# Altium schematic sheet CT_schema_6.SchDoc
size 221 x 258 mm
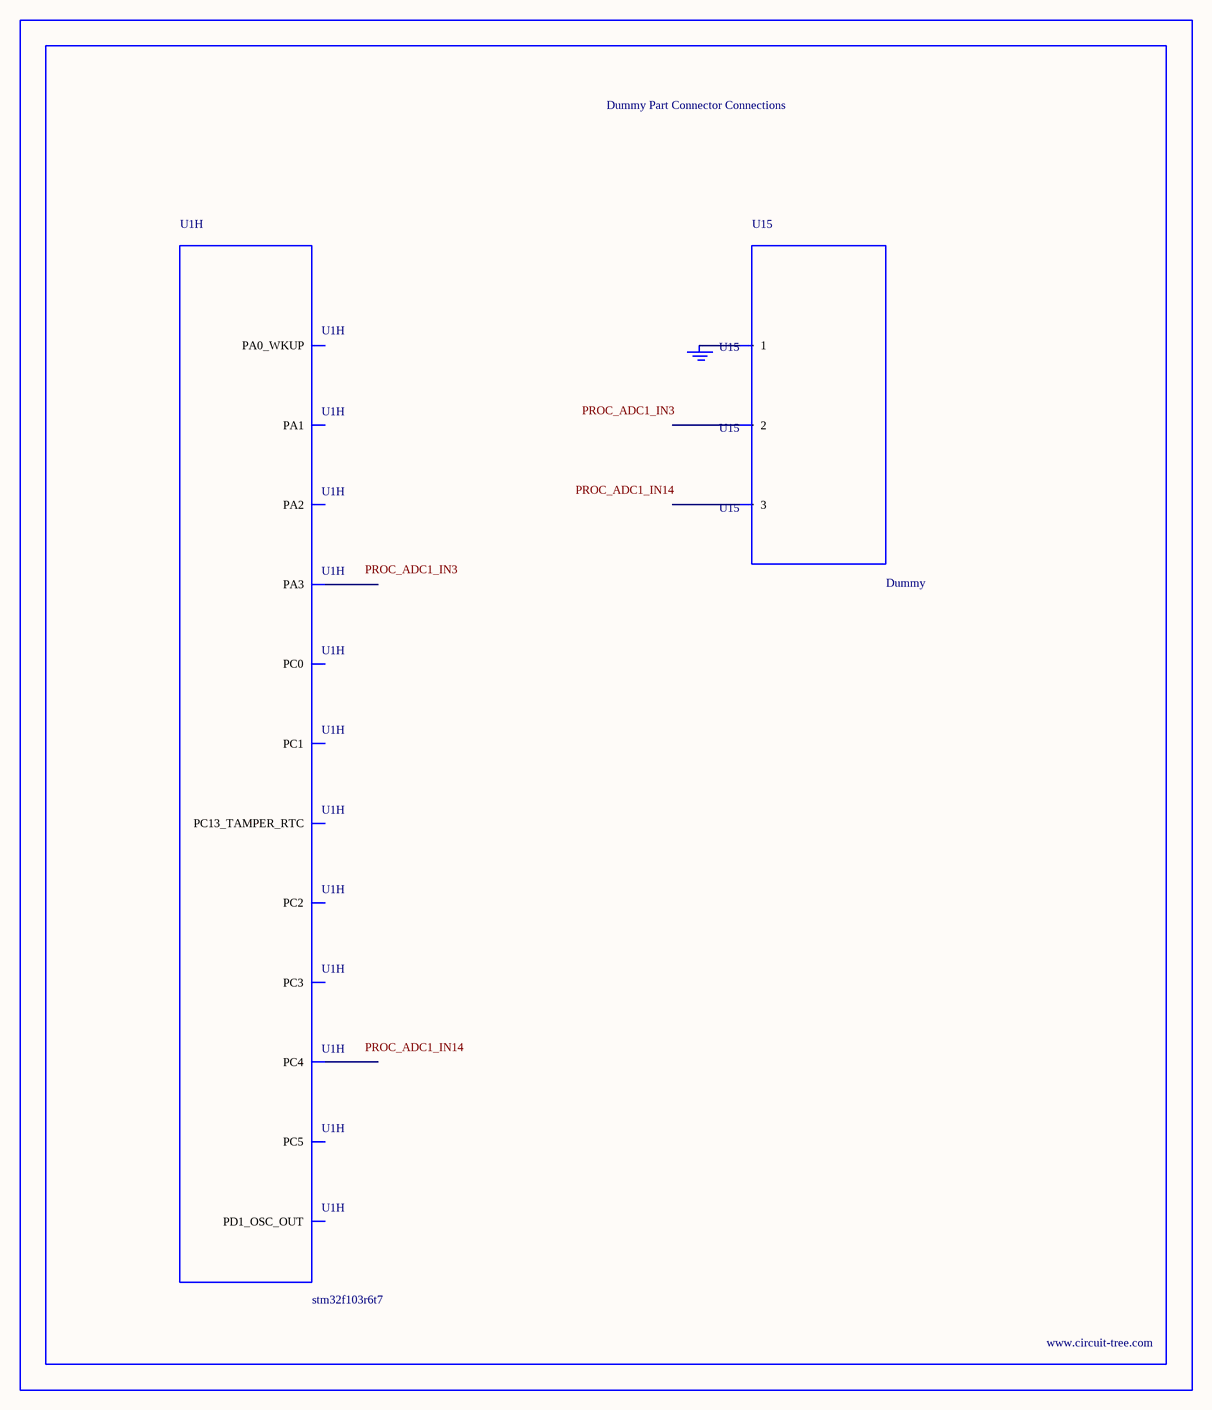
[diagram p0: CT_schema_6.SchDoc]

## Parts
BORDER5  (no value)
GND_INSTANCE_5_0  (no value)
U1  stm32f103r6t7  [LQFP64]  (part H of 8)
U15  Dummy  [DUMMY_PACKAGE_131]

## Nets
NetGND_INSTANCE_5_0_0: GND_INSTANCE_5_0.0(GND) U15.1

Not connected (* = marked no-connect by the designer): U1 2(PC13_TAMPER_RTC) 6(PD1_OSC_OUT) 8(PC0) 9(PC1) 10(PC2) 11(PC3) 14(PA0_WKUP) 15(PA1) 16(PA2) 17(PA3) 24(PC4) 25(PC5); U15 2 3

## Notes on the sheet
- Labels drawn without touching a wire or pin: PROC_ADC1_IN3, PROC_ADC1_IN14

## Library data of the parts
BORDER5 = BORDER_PAGE5
GND_INSTANCE_5_0 = GND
